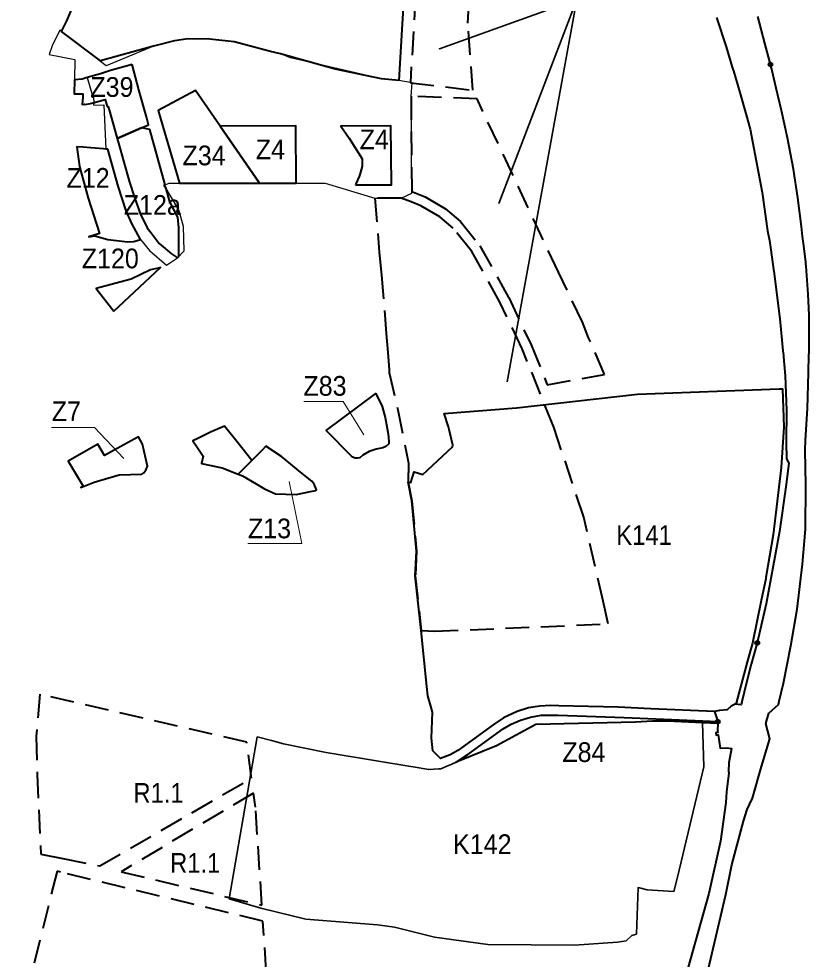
# Model space of a CAD drawing. Extents: x -650276 to -642489, y -1074311 to -1066658.
# Drawn here: x -645933 to -644970, y -1071059 to -1069915 of the extents above; entities that cross this region are included whole.
import ezdxf

# ---------------------------------------------------------------- set-up
doc = ezdxf.new("R2010")
doc.units = 0
doc.header["$LTSCALE"] = 9.6
doc.header["$PDMODE"] = 32
doc.header["$PDSIZE"] = 4.8
doc.linetypes.add('MEDIUM_DASHED', pattern=[4.5, 3, -1.5])
for name, color, linetype, lineweight in [('2', 7, 'Continuous', 40), ('3', 7, 'Continuous', 40), ('42', 7, 'Continuous', 25), ('44', 7, 'Continuous', 40), ('45', 7, 'Continuous', 40), ('46', 7, 'Continuous', 13), ('59', 7, 'Continuous', 13), ('6', 7, 'Continuous', 40), ('61', 7, 'MEDIUM_DASHED', 40), ('62', 7, 'Continuous', 35), ('7', 7, 'MEDIUM_DASHED', 40)]:
    doc.layers.add(name, color=color, linetype=linetype, lineweight=lineweight)
doc.layers.add('58', color=7, linetype='Continuous')

msp = doc.modelspace()

# ---------------------------------------------------------------- linework, layer by layer
at = {"layer": '2'}
msp.add_lwpolyline([(-645816.9, -1070270.96), (-645760.05, -1070217.79), (-645760.91, -1070217.98), (-645772.08, -1070220.39), (-645795.85, -1070231.81), (-645833.92, -1070241.96), (-645838.53, -1070243.19)], close=True, dxfattribs=at)
at = {"layer": '3'}
for points in [[(-645594.769, -1070494.065), (-645577.47, -1070490.3), (-645571.13, -1070488.89), (-645569.97, -1070488.3), (-645572.86, -1070481.41), (-645575.7, -1070477.77), (-645591.49, -1070465.19), (-645594.62, -1070462.7), (-645612.77, -1070447.82), (-645631.63, -1070435.3), (-645636.42, -1070439.93), (-645648.9, -1070452.38), (-645666.99, -1070429.58), (-645682.02, -1070410.65), (-645699.33, -1070418.25), (-645714.74, -1070425.84), (-645720.48, -1070428.75), (-645715.56, -1070436.27), (-645708.28, -1070447.28), (-645710.14, -1070456.31), (-645684.78, -1070461.52), (-645665.6, -1070469.04), (-645660.29, -1070471.12), (-645643.4, -1070481.02), (-645633.35, -1070486.91), (-645620.22, -1070493)], [(-645275.8, -1070762.66), (-645195.527, -1070765.319), (-645156.988, -1070766.884), (-645100.32, -1070769.5), (-645081.6, -1070770.362), (-645081.75, -1070772.79), (-645125.217, -1070770.81), (-645143, -1070770), (-645161, -1070770), (-645182, -1070771), (-645303, -1070774), (-645351, -1070800), (-645400.05, -1070819.84), (-645385.99, -1070810.35), (-645342.94, -1070779.31), (-645333.12, -1070773.33), (-645321.9, -1070768.47), (-645309.78, -1070764.88), (-645296.51, -1070762.52)]]:
    msp.add_lwpolyline(points, close=True, dxfattribs=at)
at = {"layer": '42'}
msp.add_lwpolyline([(-645637.56, -1070114.89), (-645559.63, -1070114.85), (-645499.129, -1070133.293), (-645466.862, -1070133.219), (-645454.051, -1070127.008), (-645455.073, -1070009.111), (-645453.852, -1069992.968), (-645469.701, -1069990.011), (-645490.814, -1069988.074), (-645601.753, -1069962.317), (-645614.072, -1069957.797), (-645625.979, -1069954.92), (-645670.325, -1069943.002), (-645699.889, -1069939.714), (-645726.542, -1069939.398), (-645742.967, -1069941.862), (-645768.424, -1069948.431), (-645826.321, -1069972.247), (-645880.431, -1069930.3), (-645882.381, -1069928.788), (-645892.09, -1069947.98), (-645895.66, -1069958.42), (-645864.48, -1069964.53), (-645864.77, -1069989.26), (-645855.54, -1069988.24), (-645849.1, -1069986.42), (-645842.8, -1070008.59), (-645843.74, -1070010.25), (-645841.43, -1070010.21), (-645841.21, -1070017.31), (-645841.89, -1070017.42), (-645841.075, -1070020.163), (-645828.963, -1070019.709), (-645826.615, -1070073.495), (-645824.28, -1070073.67), (-645811.48, -1070118.65), (-645801.99, -1070148.51), (-645795.07, -1070164.26), (-645784.51, -1070183.77), (-645773.48, -1070197.1), (-645752.54, -1070214.74), (-645739.12, -1070205.9), (-645731.3, -1070197.24), (-645731.94, -1070167.87), (-645737.63, -1070147.39), (-645755.4, -1070117.6), (-645749.28, -1070114.96), (-645737.075, -1070114.955)], close=True, dxfattribs=at)
at = {"layer": '44'}
for points in [[(-645083.31, -1069913.37), (-645071.53, -1069948.89), (-645063.96, -1069973.73), (-645063.23, -1069976.2), (-645062.57, -1069978.46), (-645061.76, -1069981.21), (-645060.612, -1069985.022), (-645054.73, -1070004.56), (-645047.28, -1070031.83), (-645042.27, -1070049.23), (-645032.21, -1070102.73), (-645027.49, -1070126.56), (-645021.14, -1070173.07), (-645018.56, -1070184.92), (-645016.92, -1070196.32), (-645013.77, -1070220.04), (-645013.51, -1070222.04), (-645005.98, -1070280.14), (-645002.308, -1070319.268), (-645001.81, -1070324.58), (-645001.64, -1070326.4)], [(-645017.46, -1069970.61), (-645018.28, -1069967.49), (-645024.45, -1069944.43), (-645032.85, -1069912.07)], [(-645010.54, -1069999.3), (-645015.548, -1069978.177), (-645016.01, -1069976.23), (-645016.89, -1069972.82), (-645017.46, -1069970.61)], [(-645166.34, -1071384.07), (-645071.99, -1070980.72), (-645064.39, -1070944.7), (-645050.47, -1070891.48), (-645045.74, -1070877.19), (-645043, -1070871.35), (-645039.25, -1070863.33), (-645028.25, -1070824.83), (-645018.18, -1070791.34), (-645023.25, -1070772.62), (-645019.57, -1070760.07), (-645007.68, -1070749.5), (-645006.739, -1070745.384), (-645001.71, -1070723.39), (-644997.14, -1070700.88), (-644992.6, -1070677.92), (-644985.04, -1070633.43), (-644978.44, -1070578.56), (-644975.05, -1070536.16), (-644974.44, -1070482.48), (-644975.29, -1070440.14), (-644974.69, -1070427.86), (-644972.48, -1070389.15), (-644971.37, -1070345.98), (-644970.61, -1070323.44), (-644970.55, -1070321.56), (-644970.524, -1070315.358), (-644970.36, -1070275.49), (-644971.47, -1070250.14), (-644974, -1070216.2), (-644974.29, -1070213.17), (-644974.49, -1070210.98), (-644976.94, -1070191.41), (-644978.49, -1070180.05), (-644979.57, -1070167.9), (-644984.21, -1070132.81), (-644989.62, -1070097.79), (-644996.88, -1070059.73), (-645004.02, -1070026.44), (-645010.54, -1069999.3)], [(-645001.64, -1070326.4), (-644999.47, -1070349.63), (-644997.87, -1070391.16), (-644998.25, -1070430.5), (-644998.17, -1070450.59), (-644995.14, -1070455.72), (-644998.92, -1070484.58), (-645006.44, -1070538.78), (-645014.07, -1070580.72), (-645022.64, -1070626.93), (-645033.53, -1070674.55)], [(-645033.53, -1070674.55), (-645041, -1070700.44), (-645046.63, -1070722.77), (-645052.4, -1070746.427), (-645053.21, -1070749.75), (-645060.46, -1070749.1), (-645065.17, -1070751.39), (-645070.3, -1070755.92), (-645079.38, -1070756.91), (-645085.58, -1070758.04), (-645081.6, -1070770.362)], [(-645081.6, -1070770.362), (-645081.75, -1070772.79), (-645081.85, -1070781.59), (-645081.57, -1070783.53), (-645083.95, -1070783.89), (-645083.49, -1070786.92), (-645081.13, -1070786.56), (-645078.85, -1070802.46), (-645070.2, -1070802.33), (-645065.01, -1070803.22), (-645068.07, -1070820.37)], [(-645068.07, -1070820.37), (-645068.52, -1070830.52), (-645068.07, -1070832.72), (-645071.18, -1070855.63), (-645071.77, -1070868.73), (-645078.23, -1070915.65)], [(-645078.23, -1070915.65), (-645092.67, -1070979.52), (-645176.14, -1071277.26), (-645204.341, -1071368.19)]]:
    msp.add_lwpolyline(points, dxfattribs=at)
msp.add_lwpolyline([(-645497.81, -1070370.93), (-645497.81, -1070370.93), (-645490.19, -1070386.97), (-645486.54, -1070400.38), (-645483.29, -1070417.99), (-645482.62, -1070423.93), (-645481.93, -1070430.04), (-645482.18, -1070432.13), (-645485.67, -1070435.7), (-645489.34, -1070437.05), (-645497.33, -1070438.82), (-645505.88, -1070441.74), (-645513.81, -1070446.24), (-645517.44, -1070449.23), (-645517.95, -1070449.45), (-645520.4, -1070449.87), (-645521.41, -1070449.84), (-645522.95, -1070449.61), (-645524.42, -1070449.16), (-645525.75, -1070448.41), (-645527.34, -1070447.1), (-645558.36, -1070416.1)], close=True, dxfattribs=at)
at = {"layer": '44', "lineweight": 13}
msp.add_lwpolyline([(-645585.63, -1070380.811), (-645537.799, -1070380.811), (-645512.608, -1070421.471)], dxfattribs=at)
msp.add_lwpolyline([(-645585.63, -1070380.811), (-645537.799, -1070380.811), (-645512.608, -1070421.471)], dxfattribs=at)
at = {"layer": '44'}
for p in [(-645017.46, -1069970.61), (-645033.53, -1070674.55), (-645081.6, -1070770.362)]:
    msp.add_point(p, dxfattribs=at)
at = {"layer": '45'}
msp.add_line((-645726.542, -1069939.398), (-645742.967, -1069941.862), dxfattribs=at)
for points in [[(-645500.137, -1069632.833), (-645498, -1069648), (-645495, -1069688), (-645495, -1069744), (-645495, -1069766), (-645504.976, -1069763.332), (-645527, -1069858), (-645459.312, -1069864.01), (-645464.288, -1069895.362), (-645465.756, -1069921.035), (-645469.701, -1069990.011)], [(-645742.967, -1069941.862), (-645768.424, -1069948.431), (-645833, -1069966), (-645880.431, -1069930.3), (-645874.219, -1069917.496), (-645869.262, -1069905.935), (-645863.95, -1069889.468), (-645857.289, -1069863.338), (-645857.204, -1069862.954), (-645850.92, -1069863.41), (-645849.79, -1069868.4), (-645808.84, -1069870.75), (-645808.28, -1069865.39), (-645804.185, -1069825.84)], [(-645469.701, -1069990.011), (-645490.814, -1069988.074), (-645547.4, -1069976.382), (-645614.072, -1069957.797), (-645625.979, -1069954.92), (-645670.325, -1069943.002), (-645699.889, -1069939.714), (-645726.542, -1069939.398)], [(-645794.679, -1069970.596), (-645821, -1069978), (-645833, -1069982)], [(-645794.679, -1069970.596), (-645821, -1069978), (-645833, -1069982)], [(-645777.143, -1070034.287), (-645786.238, -1070001.251), (-645794.679, -1069970.596)], [(-645777.143, -1070034.287), (-645786.238, -1070001.251), (-645794.679, -1069970.596)], [(-645833, -1069982), (-645849.1, -1069986.42), (-645855.54, -1069988.24), (-645864.77, -1069989.26), (-645864.97, -1070006.16), (-645854.42, -1070006.47), (-645854.65, -1070010.44), (-645855.17, -1070019.44), (-645852.36, -1070019.01), (-645852.33, -1070019.2), (-645845.37, -1070018.12), (-645845.14, -1070018.08), (-645845.17, -1070017.91), (-645841.89, -1070017.42), (-645827.365, -1070013.291), (-645825.08, -1070021.52)], [(-645833, -1069982), (-645849.1, -1069986.42), (-645855.54, -1069988.24), (-645864.77, -1069989.26), (-645864.97, -1070006.16), (-645854.42, -1070006.47), (-645854.65, -1070010.44), (-645855.17, -1070019.44), (-645852.36, -1070019.01), (-645852.33, -1070019.2), (-645845.37, -1070018.12), (-645845.14, -1070018.08), (-645845.17, -1070017.91), (-645841.89, -1070017.42), (-645827.365, -1070013.291), (-645825.08, -1070021.52)], [(-645825.08, -1070021.52), (-645823.76, -1070021.67), (-645822.549, -1070025.948), (-645812.76, -1070060.53), (-645783.063, -1070047.855), (-645774.423, -1070044.167), (-645777.143, -1070034.287)], [(-645825.08, -1070021.52), (-645823.76, -1070021.67), (-645822.549, -1070025.948), (-645812.76, -1070060.53), (-645783.063, -1070047.855), (-645774.423, -1070044.167), (-645777.143, -1070034.287)], [(-645753.182, -1070121.317), (-645755.4, -1070117.6), (-645754.333, -1070117.14), (-645772.853, -1070049.868), (-645783.063, -1070047.855), (-645812.76, -1070060.53), (-645808.721, -1070074.795), (-645804.52, -1070089.63), (-645797.66, -1070113.88), (-645791.72, -1070132.59)], [(-645824.28, -1070073.67), (-645845.01, -1070072.12), (-645854.25, -1070071.4), (-645861.74, -1070070.95), (-645858.53, -1070094.64), (-645847.88, -1070133.4)], [(-645795.07, -1070164.26), (-645801.99, -1070148.51), (-645811.48, -1070118.65), (-645824.28, -1070073.67)], [(-645737.756, -1070204.389), (-645737.624, -1070169.544), (-645738.79, -1070156.281), (-645748.62, -1070137.889), (-645753.182, -1070121.317)], [(-645847.88, -1070133.4), (-645834.31, -1070176.15), (-645847.2, -1070180.14), (-645839.82, -1070178.94), (-645824.12, -1070183.63), (-645799.91, -1070186.32), (-645792.37, -1070186.01), (-645784.51, -1070183.77), (-645795.07, -1070164.26)], [(-645791.72, -1070132.59), (-645784.83, -1070151.9), (-645776.26, -1070169.44), (-645771.246, -1070175.64)], [(-645771.246, -1070175.64), (-645761.78, -1070188.29), (-645746.73, -1070201.04), (-645739.12, -1070205.9), (-645737.756, -1070204.389)]]:
    msp.add_lwpolyline(points, dxfattribs=at)
for points in [[(-645639.638, -1070114.895), (-645687.31, -1070045.724), (-645717.36, -1070002.12), (-645762.868, -1070026.606), (-645757.215, -1070045.97), (-645737.075, -1070114.955)], [(-645639.638, -1070114.895), (-645687.31, -1070045.724), (-645717.36, -1070002.12), (-645762.868, -1070026.606), (-645757.215, -1070045.97), (-645737.075, -1070114.955)], [(-645639.638, -1070114.895), (-645594.733, -1070114.868), (-645595.2, -1070045.403), (-645687.31, -1070045.724)], [(-645639.638, -1070114.895), (-645594.733, -1070114.868), (-645595.2, -1070045.403), (-645687.31, -1070045.724)], [(-645522.587, -1070116.952), (-645478.664, -1070117.114), (-645479.429, -1070045.409), (-645540.433, -1070045.752), (-645530.3, -1070060.08), (-645514.49, -1070085.4), (-645514.56, -1070090.91), (-645514.61, -1070094.35), (-645517.02, -1070103.08), (-645518.35, -1070106.87), (-645521.73, -1070114.83)], [(-645522.587, -1070116.952), (-645478.664, -1070117.114), (-645479.429, -1070045.409), (-645540.433, -1070045.752), (-645530.3, -1070060.08), (-645514.49, -1070085.4), (-645514.56, -1070090.91), (-645514.61, -1070094.35), (-645517.02, -1070103.08), (-645518.35, -1070106.87), (-645521.73, -1070114.83)], [(-645862.66, -1070469.5), (-645853.98, -1070483.81), (-645856.87, -1070485.24), (-645840.59, -1070479), (-645810.44, -1070470.17), (-645782.57, -1070469.22), (-645780.38, -1070467.64), (-645777.8, -1070464.4), (-645776.04, -1070459.38), (-645782.13, -1070432.59), (-645786.9, -1070423.81), (-645804.58, -1070433.53), (-645828.24, -1070446.54), (-645836.32, -1070432.55), (-645872.35, -1070453.55)], [(-645862.66, -1070469.5), (-645853.98, -1070483.81), (-645856.87, -1070485.24), (-645840.59, -1070479), (-645810.44, -1070470.17), (-645782.57, -1070469.22), (-645780.38, -1070467.64), (-645777.8, -1070464.4), (-645776.04, -1070459.38), (-645782.13, -1070432.59), (-645786.9, -1070423.81), (-645804.58, -1070433.53), (-645828.24, -1070446.54), (-645836.32, -1070432.55), (-645872.35, -1070453.55)], [(-645594.769, -1070494.065), (-645577.47, -1070490.3), (-645571.13, -1070488.89), (-645569.97, -1070488.3), (-645572.86, -1070481.41), (-645575.7, -1070477.77), (-645591.49, -1070465.19), (-645594.62, -1070462.7), (-645612.77, -1070447.82), (-645631.63, -1070435.3), (-645636.42, -1070439.93), (-645648.9, -1070452.38), (-645665.6, -1070469.04), (-645660.29, -1070471.12), (-645643.4, -1070481.02), (-645633.35, -1070486.91), (-645620.22, -1070493)]]:
    msp.add_lwpolyline(points, close=True, dxfattribs=at)
at = {"layer": '46'}
msp.add_lwpolyline([(-645892.796, -1070412.223), (-645840.481, -1070412.223), (-645804.515, -1070450.215)], dxfattribs=at)
msp.add_lwpolyline([(-645892.796, -1070412.223), (-645840.481, -1070412.223), (-645804.515, -1070450.215)], dxfattribs=at)
at = {"layer": '59'}
msp.add_lwpolyline([(-645653.64, -1070553.576), (-645587.872, -1070553.576), (-645603.567, -1070478.038)], dxfattribs=at)
msp.add_lwpolyline([(-645653.64, -1070553.576), (-645587.872, -1070553.576), (-645603.567, -1070478.038)], dxfattribs=at)
at = {"layer": '6'}
for points in [[(-645435.711, -1070727.497), (-645442.836, -1070659.455), (-645442.834, -1070659.455), (-645449.82, -1070592.72), (-645448.36, -1070563), (-645454.02, -1070501.52), (-645458.46, -1070478.86), (-645455.09, -1070479.21), (-645451.226, -1070466.394), (-645440.61, -1070469.53), (-645404.4, -1070435.88), (-645404.34, -1070433.93), (-645408.66, -1070414.62), (-645409.38, -1070411.41), (-645414.65, -1070395.37), (-645326.62, -1070388.32), (-645179.26, -1070371.74), (-645006.86, -1070365.38), (-645003.102, -1070365.432), (-645003.03, -1070365.427), (-645001.312, -1070412.099), (-645004.327, -1070461.264), (-645014.277, -1070543.11), (-645023.048, -1070595.033), (-645023.346, -1070596.478)], [(-645442.834, -1070659.455), (-645449.82, -1070592.72), (-645448.36, -1070563), (-645454.02, -1070501.52), (-645458.46, -1070478.86), (-645455.09, -1070479.21), (-645451.226, -1070466.394), (-645440.61, -1070469.53), (-645404.4, -1070435.88), (-645404.34, -1070433.93), (-645408.66, -1070414.62), (-645409.38, -1070411.41), (-645414.65, -1070395.37), (-645326.62, -1070388.32), (-645179.26, -1070371.74), (-645006.86, -1070365.38), (-645003.102, -1070365.432), (-645003.03, -1070365.427), (-645001.312, -1070412.099), (-645004.327, -1070461.264), (-645014.277, -1070543.11), (-645023.048, -1070595.033), (-645023.346, -1070596.478)], [(-645023.346, -1070596.478), (-645028.384, -1070620.876), (-645039.574, -1070675.065), (-645045.493, -1070696.321), (-645059.308, -1070747.712), (-645059.421, -1070749.039), (-645060.46, -1070749.1), (-645065.17, -1070751.39), (-645070.3, -1070755.92)], [(-645023.346, -1070596.478), (-645028.384, -1070620.876), (-645039.574, -1070675.065), (-645045.493, -1070696.321), (-645059.308, -1070747.712), (-645059.421, -1070749.039), (-645060.46, -1070749.1), (-645065.17, -1070751.39), (-645070.3, -1070755.92)], [(-645435.711, -1070727.497), (-645442.836, -1070659.455), (-645442.834, -1070659.455)], [(-645275.236, -1070750.954), (-645285.11, -1070750.69), (-645298.41, -1070751.48), (-645312.2, -1070753.77), (-645325.82, -1070757.94), (-645342.41, -1070765.76), (-645354.98, -1070774.28), (-645398.04, -1070805.44), (-645407.37, -1070810.95), (-645419.18, -1070815.44), (-645424.969, -1070809.563), (-645428.39, -1070806.09), (-645430, -1070790.68), (-645428.73, -1070758.67), (-645430.84, -1070751.43), (-645434.53, -1070738.77), (-645435.711, -1070727.497)], [(-645275.236, -1070750.954), (-645285.11, -1070750.69), (-645298.41, -1070751.48), (-645312.2, -1070753.77), (-645325.82, -1070757.94), (-645342.41, -1070765.76), (-645354.98, -1070774.28), (-645398.04, -1070805.44), (-645407.37, -1070810.95), (-645419.18, -1070815.44), (-645424.969, -1070809.563), (-645428.39, -1070806.09), (-645430, -1070790.68), (-645428.73, -1070758.67), (-645430.84, -1070751.43), (-645434.53, -1070738.77), (-645435.711, -1070727.497)], [(-645070.3, -1070755.92), (-645079.38, -1070756.91), (-645085.58, -1070758.04), (-645163.06, -1070754.64), (-645202.96, -1070752.89), (-645275.236, -1070750.954)], [(-645070.3, -1070755.92), (-645079.38, -1070756.91), (-645085.58, -1070758.04), (-645163.06, -1070754.64), (-645202.96, -1070752.89), (-645275.236, -1070750.954)]]:
    msp.add_lwpolyline(points, dxfattribs=at)
at = {"layer": '6', "lineweight": 35}
for points in [[(-645100.268, -1070771.946), (-645143, -1070770), (-645161, -1070770), (-645182, -1070771), (-645303, -1070774), (-645351, -1070800), (-645400.05, -1070819.84), (-645406.09, -1070822.34), (-645409.52, -1070823.76), (-645418.67, -1070827.72), (-645421.09, -1070827.89), (-645433.49, -1070828.76), (-645452.31, -1070825.52), (-645455.184, -1070825.042)], [(-645130.749, -1070959.561), (-645098.438, -1070825.558), (-645100.268, -1070771.946)], [(-645642.52, -1070788.7), (-645676.292, -1070985.89), (-645637.94, -1070997.4), (-645583.18, -1071010.7), (-645495.87, -1071017.81)], [(-645455.184, -1070825.042), (-645494.82, -1070818.45), (-645558.3, -1070808), (-645610.25, -1070797.55), (-645625, -1070793.5), (-645642.52, -1070788.7)], [(-645495.87, -1071017.81), (-645475.01, -1071020.72), (-645426.38, -1071032.8), (-645361.54, -1071041.54), (-645255.93, -1071042.36), (-645203.66, -1071038.81), (-645193.24, -1071037.31), (-645186.18, -1071030.83), (-645180.72, -1071028.86), (-645178.73, -1070972.35), (-645167.47, -1070975.2), (-645134.973, -1070977.077), (-645134.973, -1070977.077), (-645130.749, -1070959.561)]]:
    msp.add_lwpolyline(points, dxfattribs=at)
at = {"layer": '61'}
for points in [[(-645374.642, -1069640.059), (-645376.605, -1069623.944), (-645435.877, -1069633.555), (-645431.642, -1069692.811), (-645434.826, -1069759.235), (-645443.679, -1069846.142), (-645449.445, -1069887.328), (-645455.84, -1069992.731), (-645379.881, -1070001.766), (-645385.95, -1069920.347), (-645382.14, -1069845.883), (-645378.587, -1069802.788), (-645374.542, -1069758.923), (-645371.563, -1069692.39)], [(-645374.685, -1070012.289), (-645455.073, -1070009.111), (-645454.066, -1070125.249), (-645437.885, -1070131.669), (-645413.129, -1070146.351), (-645394.98, -1070161.51), (-645371.209, -1070191.309), (-645336.176, -1070254.367), (-645308.702, -1070311.792), (-645289.153, -1070360.302), (-645219.594, -1070347.682), (-645238.856, -1070303.185), (-645246.433, -1070284.382), (-645275.729, -1070223.153)], [(-645905.795, -1070931.641), (-645879, -1070937), (-645834, -1070946), (-645649.136, -1070839.223), (-645655.04, -1070795.257), (-645907.061, -1070736.979), (-645911.345, -1070788.463), (-645910.048, -1070834.649)], [(-645646.718, -1070857.232), (-645808, -1070953), (-645636.529, -1070993.874), (-645644.425, -1070874.306)], [(-645881.661, -1070953.494), (-645885.966, -1070952.452), (-645918.57, -1071083.449), (-645932.502, -1071139.426), (-645816.47, -1071183.63), (-645741.09, -1071211.36), (-645678.86, -1071233.58), (-645640.737, -1071244.963), (-645638.935, -1071233.122), (-645631.241, -1071073.956), (-645635.256, -1071013.15)]]:
    msp.add_lwpolyline(points, close=True, dxfattribs=at)
at = {"layer": '62'}
msp.add_line((-645253.165, -1069890.903), (-645338.143, -1070356.741), dxfattribs=at)
msp.add_lwpolyline([(-645205.454, -1069890.903), (-645253.165, -1069890.903), (-645480.406, -1069576.285), (-645253.165, -1069890.903), (-645466.774, -1069697.69), (-645253.165, -1069890.903), (-645479.043, -1069805.455), (-645253.165, -1069890.903), (-645420.426, -1069951.415), (-645253.165, -1069890.903), (-645348.178, -1070139.662)], dxfattribs=at)
at = {"layer": '7'}
msp.add_lwpolyline([(-645499.142, -1070133.293), (-645493.76, -1070199.15), (-645490.95, -1070226.89), (-645485.21, -1070298.03), (-645483.34, -1070321.17), (-645481.65, -1070342.07), (-645481.67, -1070345.39), (-645471, -1070391), (-645458.32, -1070455.91), (-645458.46, -1070478.86), (-645454.02, -1070501.52), (-645448.36, -1070563), (-645449.82, -1070592.72), (-645444.47, -1070643.85), (-645442.836, -1070659.455), (-645426.34, -1070660.33), (-645214.903, -1070651.431), (-645221.272, -1070623.729), (-645244.808, -1070521.357), (-645281.252, -1070412.013), (-645319.69, -1070316.63), (-645346.844, -1070259.875), (-645381.213, -1070198.011), (-645403.604, -1070169.942), (-645420.081, -1070156.179), (-645443.191, -1070142.473), (-645454.881, -1070137.836), (-645466.862, -1070133.22)], close=True, dxfattribs=at)

# ---------------------------------------------------------------- texts
at = {"layer": '2', "width": 0.95}
msp.add_text('Z120', height=24, dxfattribs=at).set_placement((-645855.898, -1070218.668))
at = {"layer": '44', "width": 0.95}
msp.add_text('Z83', height=24, dxfattribs=at).set_placement((-645586.057, -1070373.732))
msp.add_text('Z83', height=24, dxfattribs=at).set_placement((-645586.057, -1070373.732))
at = {"layer": '46', "width": 0.95}
for s, p in [('Z39', (-645845.387, -1070009.975)), ('Z39', (-645845.387, -1070009.975)), ('Z4', (-645517.623, -1070073.78)), ('Z4', (-645517.623, -1070073.78)), ('Z4', (-645644.02, -1070085.964)), ('Z4', (-645644.02, -1070085.964)), ('Z34', (-645733.26, -1070093.266)), ('Z34', (-645733.26, -1070093.266)), ('Z12', (-645874.409, -1070120.563)), ('Z12a', (-645804.738, -1070153.542)), ('Z7', (-645892.427, -1070404.622)), ('Z7', (-645892.427, -1070404.622))]:
    msp.add_text(s, height=24, dxfattribs=at).set_placement(p)
at = {"layer": '58'}
for s, width, p in [('K141', 0.9, (-645205.123, -1070555.263)), ('K142', 0.95, (-645403.889, -1070931.543))]:
    msp.add_text(s, height=24, dxfattribs=dict(at, width=width)).set_placement(p)
at = {"layer": '59', "width": 0.95}
for s, p in [('Z13', (-645653.625, -1070547.221)), ('Z84', (-645270.865, -1070819.478))]:
    msp.add_text(s, height=24, dxfattribs=at).set_placement(p)
at = {"layer": '62', "width": 0.9}
for p in [(-645792.947, -1070869.095), (-645748.253, -1070954.32)]:
    msp.add_text('R1.1', height=24, dxfattribs=at).set_placement(p)

doc.saveas('drawing.dxf')
